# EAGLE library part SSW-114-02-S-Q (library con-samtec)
THROUGH-HOLE .025" SQ POST SOCKET Source: Samtec SSW.pdf
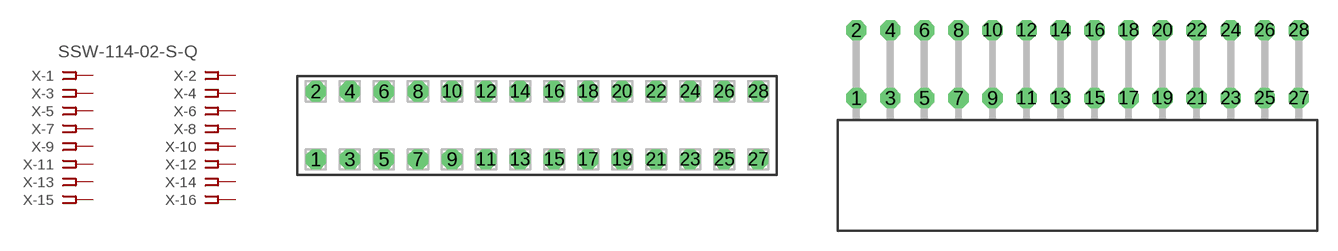
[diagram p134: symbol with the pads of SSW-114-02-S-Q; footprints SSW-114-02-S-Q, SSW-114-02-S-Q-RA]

Designator prefix X; gates -1=FPINV -2=FPIN -3=FPIN -4=FPIN -5=FPIN -6=FPIN -7=FPIN -8=FPIN -9=FPIN -10=FPIN -11=FPIN -12=FPIN -13=FPIN -14=FPIN -15=FPIN -16=FPIN -17=FPIN -18=FPIN -19=FPIN -20=FPIN -21=FPIN -22=FPIN -23=FPIN -24=FPIN -25=FPIN -26=FPIN -27=FPIN -28=FPIN

## SSW-114-02-S-Q (OC_FARNELL: unknown; OC_NEWARK: unknown)  [SSW-114-02-S-Q]
1  -1:1  pas
2  -2:1  pas
3  -3:1  pas
4  -4:1  pas
5  -5:1  pas
6  -6:1  pas
7  -7:1  pas
8  -8:1  pas
9  -9:1  pas
10  -10:1  pas
11  -11:1  pas
12  -12:1  pas
13  -13:1  pas
14  -14:1  pas
15  -15:1  pas
16  -16:1  pas
17  -17:1  pas
18  -18:1  pas
19  -19:1  pas
20  -20:1  pas
21  -21:1  pas
22  -22:1  pas
23  -23:1  pas
24  -24:1  pas
25  -25:1  pas
26  -26:1  pas
27  -27:1  pas
28  -28:1  pas

## SSW-114-02-S-QRA (OC_FARNELL: unknown; OC_NEWARK: unknown)  [SSW-114-02-S-Q-RA]
Pads as for SSW-114-02-S-Q

## Footprint SSW-114-02-S-Q (pad centres in mm)
THROUGH-HOLE .025" SQ POST SOCKET Source: Samtec SSW.pdf
drill 1 pad 1.5 octagon: 1 -16.51,-2.54; 2 -16.51,2.54; 3 -13.97,-2.54; 4 -13.97,2.54; 5 -11.43,-2.54; 6 -11.43,2.54; 7 -8.89,-2.54; 8 -8.89,2.54; 9 -6.35,-2.54; 10 -6.35,2.54; 11 -3.81,-2.54; 12 -3.81,2.54; 13 -1.27,-2.54; 14 -1.27,2.54; 15 1.27,-2.54; 16 1.27,2.54; 17 3.81,-2.54; 18 3.81,2.54; 19 6.35,-2.54; 20 6.35,2.54; 21 8.89,-2.54; 22 8.89,2.54; 23 11.43,-2.54; 24 11.43,2.54; 25 13.97,-2.54; 26 13.97,2.54; 27 16.51,-2.54; 28 16.51,2.54

## Footprint SSW-114-02-S-Q-RA (pad centres in mm)
THROUGH-HOLE .025" SQ POST SOCKET Source: Samtec SSW.pdf
drill 1 pad 1.5 octagon: 1 -16.51,1.524; 2 -16.51,6.604; 3 -13.97,1.524; 4 -13.97,6.604; 5 -11.43,1.524; 6 -11.43,6.604; 7 -8.89,1.524; 8 -8.89,6.604; 9 -6.35,1.524; 10 -6.35,6.604; 11 -3.81,1.524; 12 -3.81,6.604; 13 -1.27,1.524; 14 -1.27,6.604; 15 1.27,1.524; 16 1.27,6.604; 17 3.81,1.524; 18 3.81,6.604; 19 6.35,1.524; 20 6.35,6.604; 21 8.89,1.524; 22 8.89,6.604; 23 11.43,1.524; 24 11.43,6.604; 25 13.97,1.524; 26 13.97,6.604; 27 16.51,1.524; 28 16.51,6.604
